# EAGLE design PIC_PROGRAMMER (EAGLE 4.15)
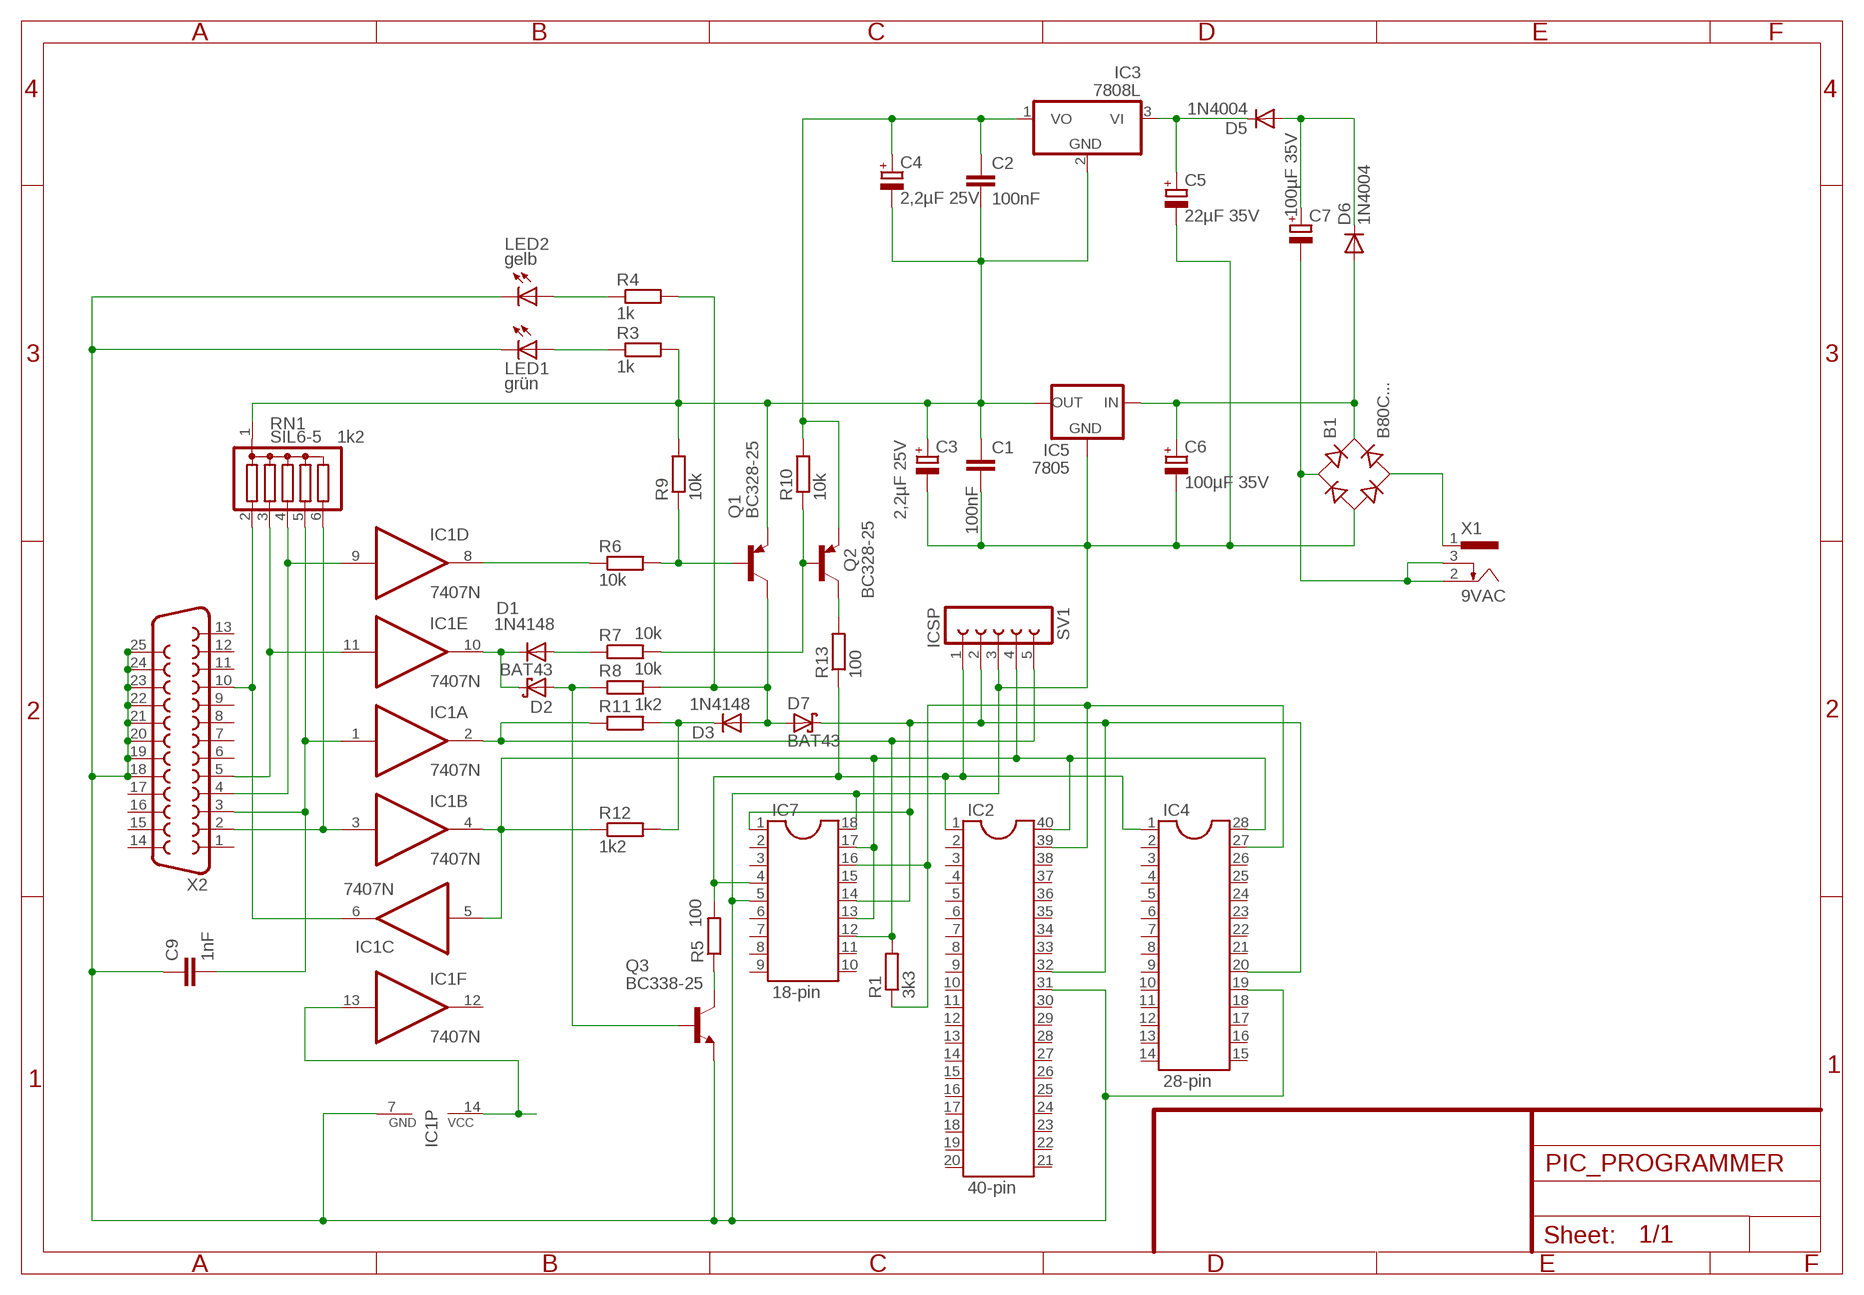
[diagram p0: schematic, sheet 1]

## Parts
B1  B80C...  RB1A  [RB1A]
C1  100nF  C-EU050-030X075  [C050-030X075]
C2  100nF  C-EU050-030X075  [C050-030X075]
C3  2,2µF 25V  CPOL-EUE2.5-5  [E2,5-5]
C4  2,2µF 25V  CPOL-EUE2.5-5  [E2,5-5]
C5  22µF 35V  CPOL-EUE5-8.5  [E5-8,5]
C6  100µF 35V  CPOL-EUE5-8.5  [E5-8,5]
C7  100µF 35V  CPOL-EUE5-8.5  [E5-8,5]
C9  1nF  C-EU050-025X075  [C050-025X075]
D1  1N4148  [DO35-10]
D2  BAT43  [DO35-10]
D3  1N4148  [DO35-10]
D5  1N4004  [DO41-10]
D6  1N4004  [DO41-10]
D7  BAT43  [DO35-10]
IC1  7407N  [DIL14]
IC2  40-pin  TEXTOOL40  [TEXTOOL40]
IC3  7808L  [TO92]
IC4  28-pin  DIL28-3  [DIL28-3]
IC5  7805  78XXS  [78XXS]
IC7  18-pin  TEXTOOL18  [TEXTOOL18]
LED1  grün  LED5MM  [LED5MM]
LED2  gelb  LED5MM  [LED5MM]
Q1  BC328-25  [TO92-EBC]
Q2  BC328-25  [TO92-EBC]
Q3  BC338-25  [TO92-EBC]
R1  3k3  R-EU_0207/10  [0207/10]
R3  1k  R-EU_0207/10  [0207/10]
R4  1k  R-EU_0207/10  [0207/10]
R5  100  R-EU_0207/10  [0207/10]
R6  10k  R-EU_0207/10  [0207/10]
R7  10k  R-EU_0207/10  [0207/10]
R8  10k  R-EU_0207/10  [0207/10]
R9  10k  R-EU_0207/10  [0207/10]
R10  10k  R-EU_0207/10  [0207/10]
R11  1k2  R-EU_0207/10  [0207/10]
R12  1k2  R-EU_0207/10  [0207/10]
R13  100  R-EU_0207/10  [0207/10]
RN1  SIL6-5 1k2  G05R  [SIL6]
SV1  ICSP  FE05-1  [FE05-1]
X1  9VAC  733989-55  [733989-5]
X2  F25H  [F25H]

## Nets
5VGESCH: D3.A D7.A Q1.C R4.2 R8.2
13V: C2.1 C4.+ IC3.1(VO) Q2.E R10.2
DATA_IN: IC1.3(B:I) RN1.6 X2.2
DATA_OUT: IC1.6(C:O) RN1.2 X2.10
GND [GND]: B1.- C1.2 C3.- C5.- C6.- C9.1 IC1.7(P:GND) IC2.31 IC4.19 IC5.GND IC7.5 IC7.18 LED1.K(C) LED2.K(C) Q3.E SV1.3 X2.18 X2.19 X2.20 X2.21 X2.22 X2.23 X2.24 X2.25
ICSP_CLK: IC1.2(A:O) IC7.12 R1.2 R11.1 SV1.5
ICSP_DATA: IC1.4(B:O) IC1.5(C:I) IC2.40 IC4.28 IC7.13 IC7.17 R12.1 SV1.4
MCLR: IC2.1 IC4.1 IC7.4 R5.2 R13.1 SV1.1
N$1: IC1.9(D:I) RN1.4 X2.4
N$2: IC1.11(E:I) RN1.3 X2.5
N$3: C9.2 IC1.1(A:I) RN1.5 X2.3
N$4: D3.C R11.2 R12.2
N$5: IC2.39 IC4.27 IC7.16 R1.1
N$6: IC1.8(D:O) R6.1
N$7: B1.+ C6.+ D6.A IC5.IN
N$8: Q2.C R13.2
N$9: B1.AC1 C7.- X1.2 X1.3
N$10: C5.+ D5.C IC3.3(VI)
N$11: C7.+ D5.A D6.C
N$12: Q3.C R5.1
N$13: B1.AC2 X1.1
N$14: D1.C D2.C IC1.10(E:O)
N$15: LED1.A R3.1
N$16: LED2.A R4.1
N$17: Q1.B R6.2 R9.1
N$18: D1.A R7.1
N$19: Q2.B R7.2 R10.1
N$21: D2.A Q3.B R8.1
VCC [GND]: C1.1 C2.2 C3.+ C4.- IC1.13(F:I) IC1.14(P:VCC) IC3.2(GND) IC5.OUT Q1.E R3.2 R9.2 RN1.1
VDD: D7.C IC2.32 IC4.20 IC7.1 IC7.14 SV1.2
Unconnected: IC1.12(F:O) IC2.2 IC2.3 IC2.4 IC2.5 IC2.6 IC2.7 IC2.8 IC2.9 IC2.10 IC2.11 IC2.12 IC2.13 IC2.14 IC2.15 IC2.16 IC2.17 IC2.18 IC2.19 IC2.20 IC2.21 IC2.22 IC2.23 IC2.24 IC2.25 IC2.26 IC2.27 IC2.28 IC2.29 IC2.30 IC2.33 IC2.34 IC2.35 IC2.36 IC2.37 IC2.38 IC4.2 IC4.3 IC4.4 IC4.5 IC4.6 IC4.7 IC4.8 IC4.9 IC4.10 IC4.11 IC4.12 IC4.13 IC4.14 IC4.15 IC4.16 IC4.17 IC4.18 IC4.21 IC4.22 IC4.23 IC4.24 IC4.25 IC4.26 IC7.2 IC7.3 IC7.6 IC7.7 IC7.8 IC7.9 IC7.10 IC7.11 IC7.15 X2.1 X2.6 X2.7 X2.8 X2.9 X2.11 X2.12 X2.13 X2.14 X2.15 X2.16 X2.17

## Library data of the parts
B1 = rectifier:RB1A: RECTIFIER 1 A
C1 C2 C9 = rcl:C-EU: CAPACITOR, European symbol
C3-C7 = rcl:CPOL-EU: POLARIZED CAPACITOR, European symbol
D1 D3 = diode:1N4148: DIODE
D2 D7 = sprut:BAT43: DIODE
D5 D6 = diode:1N4004: DIODE
IC1 = 74xx-eu:74*07: Hex BUFFER, open collector high-voltage output
IC2 = sprut:TEXTOOL40: Dual In Line
IC3 = linear:78*: Positive VOLTAGE REGULATOR
IC4 = ic-package:DIL28: Dual In Line
IC5 = v-reg:78XXS: VOLTAGE REGULATOR
IC7 = sprut:TEXTOOL18: Dual In Line
LED1 LED2 = led:LED: LED
Q1 Q2 = transistor-pnp:BC328*: PNP Transistror
Q3 = transistor-npn:BC338*: NPN Transistor
R1 R3-R13 = rcl:R-EU_: RESISTOR, European symbol
RN1 = resistor-sil:G05R: SIL RESISTOR
SV1 = con-lsta:FE05-1: FEMALE HEADER
X1 = con-conrad:733989-55: FEMALE PRINT CONNECTOR 1.1 mm, FUK HING Industries, distributor Conrad
X2 = con-subd:F25: SUB-D

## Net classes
1 GND: width 1.016 mm

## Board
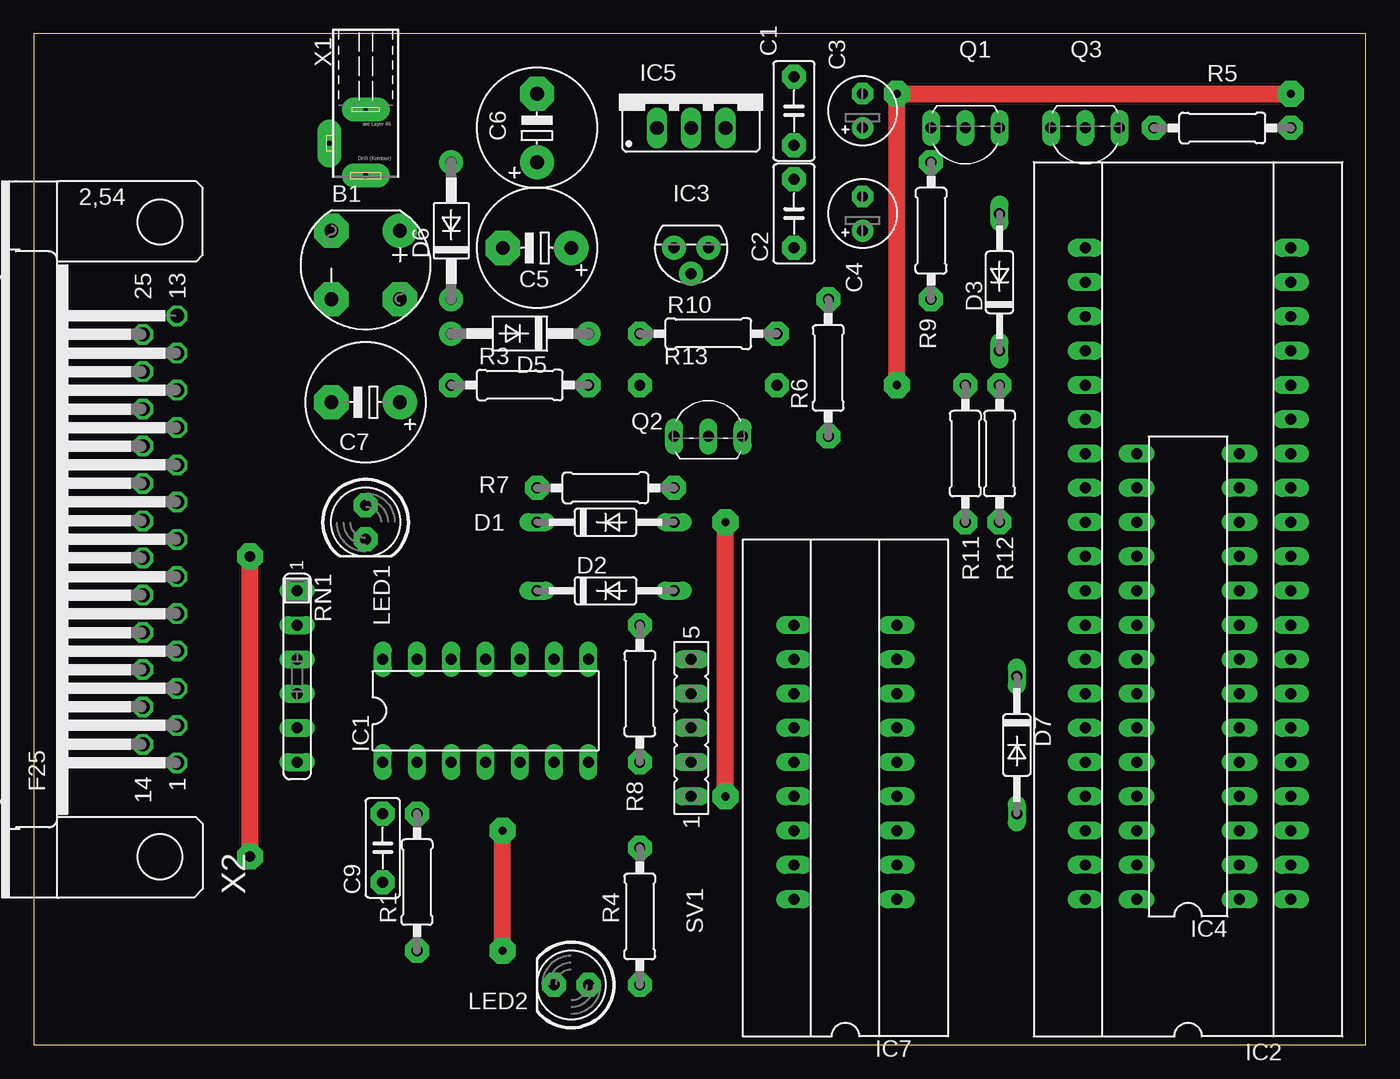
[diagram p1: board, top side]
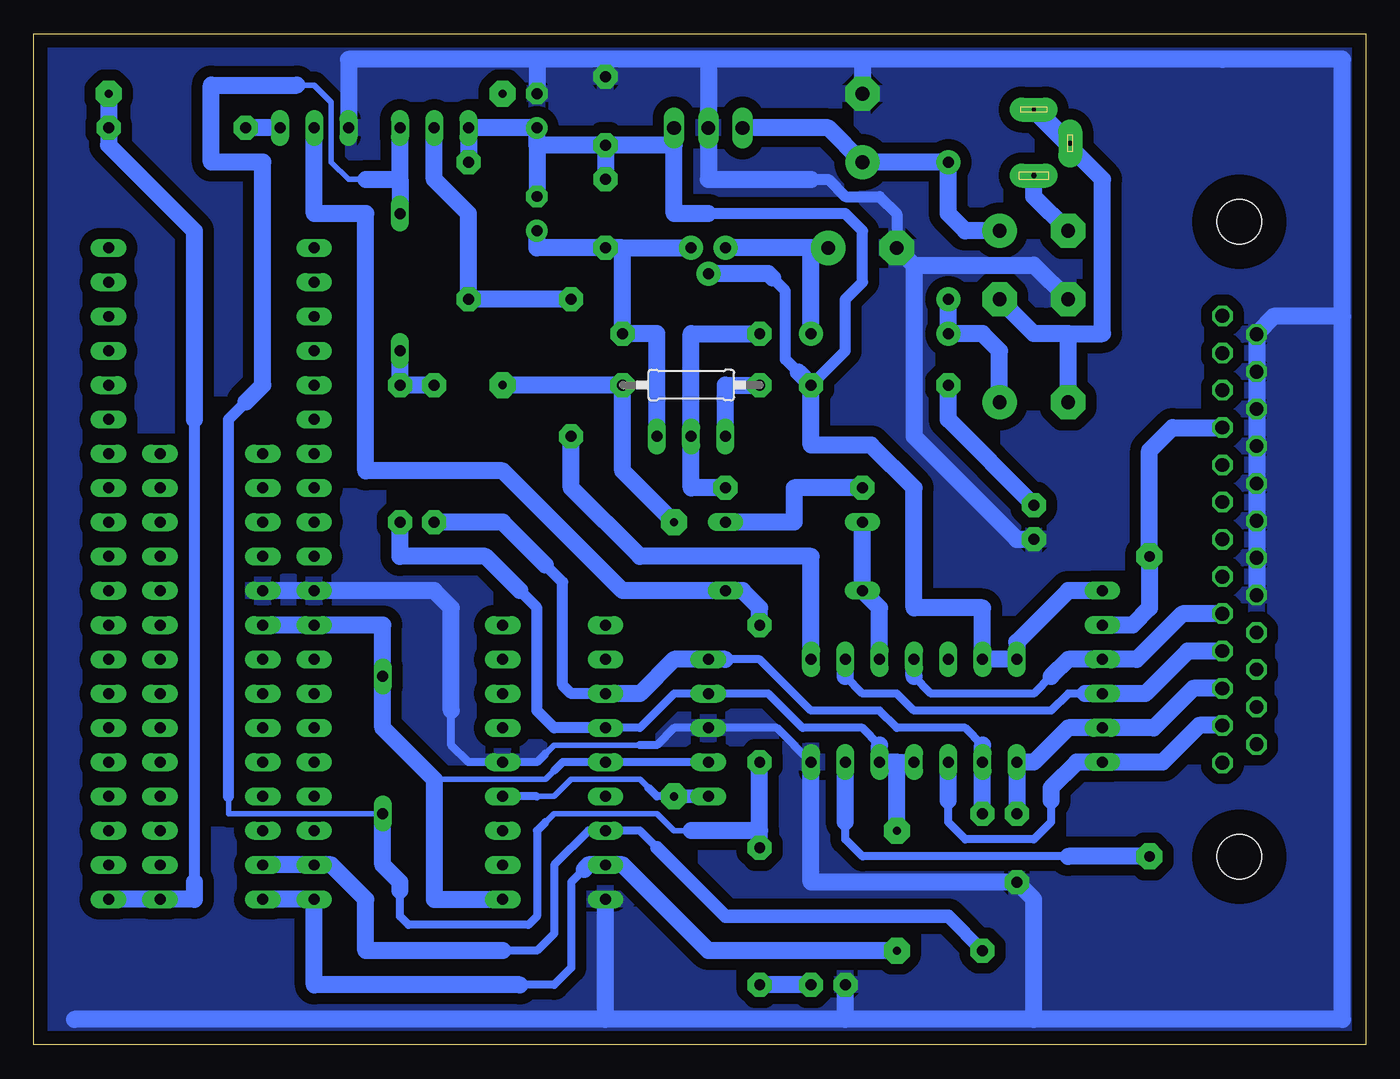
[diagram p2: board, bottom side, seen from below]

Size 98.73 x 74.92 mm. Coordinates in mm from the lower left corner, seen from the top.
Outline: 0,0 98.73,0 98.73,74.92 0,74.92 0,0
Copper layers (1*16): Top 0.035mm / dielectric 1.5mm / Bottom 0.035mm
Design rules "leiterplatte mit löchern": minimum track width 10mil, minimum drill 8mil, track to track 8mil, track to pad 8mil, pad to pad 8mil, via to via 8mil, smd to smd 8mil, copper to edge 40mil, drill to drill 8mil, minimum pad ring 10mil, minimum via ring 10mil, stop-mask expansion 4mil, vias tented up to drill 0mil, thermal gap 10mil

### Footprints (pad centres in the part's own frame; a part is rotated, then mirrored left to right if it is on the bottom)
RB1A = drill 1.016 pad 2.54 round: + -2.54,2.54 | drill 1.016 pad 2.54 octagon: - 2.54,-2.54; AC1 2.54,2.54; AC2 -2.54,-2.54
C050-030X075 = drill 0.813 pad 1.778 octagon: 1 -2.54,0; 2 2.54,0
E2,5-5 = drill 0.813 pad 1.6 round: + -1.27,0 | drill 0.813 pad 1.6 octagon: - 1.27,0
E5-8,5 = drill 1.016 pad 2.54 round: + -2.54,0 | drill 1.016 pad 2.54 octagon: - 2.54,0
C050-025X075 = drill 0.813 pad 1.778 octagon: 1 -2.54,0; 2 2.54,0
DO35-10 = drill 0.813 long: A 5.08,0; C -5.08,0
DO41-10 = drill 0.813 pad 1.778 round: A 5.08,0; C -5.08,0
DIL14 = drill 0.813 long: 1 -7.62,-3.81; 2 -5.08,-3.81; 3 -2.54,-3.81; 4 0,-3.81; 5 2.54,-3.81; 6 5.08,-3.81; 7 7.62,-3.81; 8 7.62,3.81; 9 5.08,3.81; 10 2.54,3.81; 11 0,3.81; 12 -2.54,3.81; 13 -5.08,3.81; 14 -7.62,3.81
TEXTOOL40 = drill 0.813 long: 1 -24.13,-7.62; 2 -21.59,-7.62; 3 -19.05,-7.62; 4 -16.51,-7.62; 5 -13.97,-7.62; 6 -11.43,-7.62; 7 -8.89,-7.62; 8 -6.35,-7.62; 9 -3.81,-7.62; 10 -1.27,-7.62; 11 1.27,-7.62; 12 3.81,-7.62; 13 6.35,-7.62; 14 8.89,-7.62; 15 11.43,-7.62; 16 13.97,-7.62; 17 16.51,-7.62; 18 19.05,-7.62; 19 21.59,-7.62; 20 24.13,-7.62; 21 24.13,7.62; 22 21.59,7.62; 23 19.05,7.62; 24 16.51,7.62; 25 13.97,7.62; 26 11.43,7.62; 27 8.89,7.62; 28 6.35,7.62; 29 3.81,7.62; 30 1.27,7.62; 31 -1.27,7.62; 32 -3.81,7.62; 33 -6.35,7.62; 34 -8.89,7.62; 35 -11.43,7.62; 36 -13.97,7.62; 37 -16.51,7.62; 38 -19.05,7.62; 39 -21.59,7.62; 40 -24.13,7.62
TO92 = drill 0.813 pad 1.778 round: 1 -1.27,0; 2 0,1.905; 3 1.27,0
DIL28-3 = drill 0.813 long: 1 -16.51,-3.81; 2 -13.97,-3.81; 3 -11.43,-3.81; 4 -8.89,-3.81; 5 -6.35,-3.81; 6 -3.81,-3.81; 7 -1.27,-3.81; 8 1.27,-3.81; 9 3.81,-3.81; 10 6.35,-3.81; 11 8.89,-3.81; 12 11.43,-3.81; 13 13.97,-3.81; 14 16.51,-3.81; 15 16.51,3.81; 16 13.97,3.81; 17 11.43,3.81; 18 8.89,3.81; 19 6.35,3.81; 20 3.81,3.81; 21 1.27,3.81; 22 -1.27,3.81; 23 -3.81,3.81; 24 -6.35,3.81; 25 -8.89,3.81; 26 -11.43,3.81; 27 -13.97,3.81; 28 -16.51,3.81
78XXS = drill 1.016 long: GND 0,-2.54; IN -2.54,-2.54; OUT 2.54,-2.54
TEXTOOL18 = drill 0.813 long: 1 -10.16,-3.81; 2 -7.62,-3.81; 3 -5.08,-3.81; 4 -2.54,-3.81; 5 0,-3.81; 6 2.54,-3.81; 7 5.08,-3.81; 8 7.62,-3.81; 9 10.16,-3.81; 10 10.16,3.81; 11 7.62,3.81; 12 5.08,3.81; 13 2.54,3.81; 14 0,3.81; 15 -2.54,3.81; 16 -5.08,3.81; 17 -7.62,3.81; 18 -10.16,3.81
LED5MM = drill 0.813 pad 1.778 octagon: A -1.27,0; K 1.27,0
TO92-EBC = drill 0.813 long: B 0,-1.27; C -2.54,-1.27; E 2.54,-1.27
0207/10 = drill 0.813 pad 1.778 octagon: 1 -5.08,0; 2 5.08,0
SIL6 = drill 0.813 long: 1 -6.35,0; 2 -3.81,0; 3 -1.27,0; 4 1.27,0; 5 3.81,0; 6 6.35,0
FE05-1 = drill 0.813 long: 1 -5.08,0; 2 -2.54,0; 3 0,0; 4 2.54,0; 5 5.08,0
733989-5 = drill 0.4 pad 1.778 long: 1 0,5.82; 3 2.7,3.42 | drill 0.3 pad 1.778 long: 2 0,0.92
F25H = drill 1.016 octagon: 1 -16.561,-1.27; 2 -13.792,-1.27; 3 -11.049,-1.27; 4 -8.28,-1.27; 5 -5.512,-1.27; 6 -2.769,-1.27; 7 0,-1.27; 8 2.769,-1.27; 9 5.512,-1.27; 10 8.28,-1.27; 11 11.049,-1.27; 12 13.792,-1.27; 13 16.561,-1.27; 14 -15.189,1.27; 15 -12.421,1.27; 16 -9.652,1.27; 17 -6.909,1.27; 18 -4.14,1.27; 19 -1.372,1.27; 20 1.372,1.27; 21 4.14,1.27; 22 6.909,1.27; 23 9.652,1.27; 24 12.421,1.27; 25 15.189,1.27 | hole 3.302: -23.52,0; 23.52,0

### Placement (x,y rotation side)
B1  24.6,57.78 270 top
C1  56.35,69.21 90 top
C2  56.35,61.59 90 top
C3  61.43,69.21 90 top
C4  61.43,61.59 90 top
C5  37.3,59.05 180 top
C6  37.3,67.94 90 top
C7  24.6,47.62 180 top
C9  25.87,14.6 90 top
D1  42.38,38.73 0 top
D2  42.38,33.65 0 top
D3  71.59,56.51 90 top
D5  36.03,52.7 180 top
D6  30.95,60.32 90 top
D7  72.86,22.22 270 top
IC1  33.49,24.76 0 top
IC2  85.56,34.92 90 top
IC3  48.73,59.05 180 top
IC4  85.56,27.3 90 top
IC5  48.73,70.48 0 top
IC7  60.16,20.95 90 top
LED1  24.6,38.73 270 top
LED2  39.84,4.44 180 top
Q1  69.05,66.67 180 top
Q2  50,46.35 0 top
Q3  77.94,66.67 180 top
R1  28.41,12.06 90 top
R3  36.03,48.89 0 top
R4  44.92,9.52 90 top
R5  88.1,67.94 0 top
R6  58.89,50.16 90 top
R7  42.38,41.27 0 top
R8  44.92,26.03 270 top
R9  66.51,60.32 90 top
R10  50,52.7 0 top
R11  69.05,43.81 90 top
R12  71.59,43.81 90 top
R13  50,48.89 0 bottom
RN1  19.52,27.3 270 top
SV1  48.73,23.49 90 top
X1  24.6,70.23 180 top
X2  9.36,37.46 90 top

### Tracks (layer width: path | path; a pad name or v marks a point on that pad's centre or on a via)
5VGESCH
  Bottom 0.406: D7.A 84.29,17.14 84.29,18.41 | 74.13,64.13 75.4,64.13 76.67,65.4 76.67,69.84 77.94,71.12 79.21,71.12 | 50,15.87 51.27,15.87 52.54,17.14 60.16,17.14 60.8,16.5
  Bottom 0.61: 71.59,11.43 71.59,9.52 70.95,8.88 62.07,8.88 61.43,9.52 61.43,15.87 60.8,16.5
  Bottom 0.813: 83.02,47.62 84.29,46.35 84.29,18.41
  Bottom 1.27: R4.2 44.92,15.87 | 44.92,15.87 R8.2 | D7.A 72.86,13.33 71.59,12.06 71.59,11.43 | 71.59,64.13 Q1.C | 71.59,64.13 D3.A | 74.13,64.13 71.59,64.13 | 79.21,71.12 85.56,71.12 85.56,65.4 81.75,65.4 81.75,48.89 83.02,47.62 | 44.92,15.87 50,15.87
13V
  Bottom 1.27: 55.08,59.05 IC3.1 | 55.08,59.05 C2.1 61.43,59.05 C4.+ | 55.08,59.05 R10.2 52.54,52.7 Q2.E
DATA_IN
  Bottom 0.61: 30.95,18.09 30.95,16.5 29.68,15.23 24.6,15.23 23.33,16.5 23.33,18.09
  Bottom 1.27: 30.95,18.09 IC1.3 | 23.33,18.09 23.33,19.04 21.43,20.95 RN1.6 15.07,20.95 12.35,23.68 10.66,23.68 X2.2
DATA_OUT  (via drill 0.8 pad 1.93)
  Top 1.27: v16.03,13.96 v16.03,36.19
  Bottom 0.61: 22.06,13.96 37.3,13.96 38.57,15.23 38.57,16.5
  Bottom 1.27: 38.57,16.5 IC1.6 | X2.10 14.33,45.74 16.03,44.03 v16.03,36.19 16.03,32.38 17.3,31.11 RN1.2 | v16.03,13.96 22.06,13.96
GND
  Bottom 0.406: 60.8,21.59 60.16,22.22 53.81,22.22
  Bottom 0.61: IC1.7 43.65,23.49 SV1.3 51.27,23.49 52.54,22.22 53.81,22.22 | 1.74,73.02 1.76,73.05 | 60.8,21.59 61.43,20.95 IC7.5 66.51,20.95 67.78,22.22 67.78,24.76
  Bottom 0.813: 41.11,64.13 39.84,64.13 38.57,62.86 36.03,62.86 34.76,61.59 C5.-
  Bottom 1.27: 24.6,1.9 1.74,1.9 1.74,53.97 | 24.6,1.9 38.57,1.9 | 38.57,1.9 56.35,1.9 | 56.35,1.9 95.72,1.9 | 1.74,53.97 1.74,73.02 | IC4.19 IC2.31 69.05,33.65 67.78,32.38 67.78,24.76 | 56.35,1.9 IC7.18 | IC1.7 41.11,12.06 C9.1 24.6,10.79 24.6,1.9 | 38.57,1.9 LED2.K | 37.3,73.02 C6.- | 37.3,73.02 48.73,73.02 | 48.73,73.02 IC5.GND 48.73,64.13 41.11,64.13 | B1.- 24.6,57.78 33.49,57.78 | C5.- 33.49,57.78 | 1.76,73.05 10.63,73.02 37.3,73.02 | 56.35,73.02 C1.2 | 61.43,73.02 C3.- | 56.35,73.02 61.43,73.02 | 48.73,73.02 56.35,73.02 | Q3.E 75.4,73.02 61.43,73.02 | LED1.K 25.87,37.46 33.49,45.08 33.49,57.78 | 1.74,53.97 6.82,53.97 8.09,52.7 X2.25 X2.24 8.09,47.62 | 8.09,47.62 X2.23 | 8.09,47.62 X2.22 X2.21 | X2.21 8.09,41.59 | X2.20 8.09,38.73 | X2.21 X2.20 | X2.20 X2.19 X2.18
  pour Bottom (isolate 0.813): -2.07,-0.64 99.53,-0.64 99.53,75.56 -2.07,75.56
ICSP_CLK
  Bottom 0.61: 28.41,22.22 29.68,23.49 34.76,23.49 36.03,24.76 41.11,24.76 44.92,28.57 47.46,28.57
  Bottom 0.813: 60.8,35.56 59.53,34.29 59.53,26.66 58.89,26.03 IC7.12
  Bottom 1.27: 28.41,22.22 IC1.2 R1.2 | IC7.12 53.81,26.03 51.27,28.57 SV1.5 47.46,28.57 | R11.1 63.97,38.73 60.8,35.56
ICSP_DATA  (via drill 0.61 pad 1.93)
  Top 1.27: v34.76,6.98 v34.76,15.87
  Bottom 0.61: 36.03,22.22 37.3,23.49 41.75,23.49 44.29,26.03 SV1.4 51.27,26.03 53.81,23.49 IC7.13 | 62.7,4.44 60.16,4.44 58.89,5.71 58.89,12.06 57.94,13.01
  Bottom 0.813: 62.7,33.65 61.43,32.38 61.43,24.76 60.16,23.49 IC7.13
  Bottom 1.27: 34.76,20.95 IC1.4 | 34.76,20.95 IC1.5 36.03,22.22 | IC4.28 IC2.40 77.94,4.44 62.7,4.44 | v34.76,6.98 48.73,6.98 55.08,13.33 IC7.17 57.62,13.33 57.94,13.01 | v34.76,15.87 34.76,20.95 | R12.1 71.59,36.19 65.24,36.19 62.7,33.65
MCLR  (via drill 0.61 pad 1.93)
  Top 1.27: v51.27,18.41 v51.27,38.73 | v63.97,48.89 v63.97,70.48 v93.18,70.48
  Bottom 0.406: 61.43,18.41 60.16,18.41 58.89,19.68 53.81,19.68 53.18,19.04
  Bottom 0.61: 61.43,18.41 IC7.4 | 53.18,19.04 52.54,18.41 v51.27,18.41
  Bottom 0.813: 86.83,46.35 86.83,12.06
  Bottom 1.016: SV1.1 v51.27,18.41
  Bottom 1.27: IC2.1 IC4.1 86.83,10.79 86.83,12.06 | 86.83,46.35 86.83,60.32 93.18,66.67 R5.2 v93.18,70.48 | R13.1 55.08,42.54 v51.27,38.73 | R13.1 v63.97,48.89 R13.1
N$1
  Bottom 0.61: 38.57,27.3 37.3,26.03 34.76,26.03 33.49,24.76 23.33,24.76 22.06,26.03 20.79,26.03
  Bottom 1.27: 38.57,27.3 IC1.9 | 20.79,26.03 RN1.4 16.34,26.03 13.19,29.18 10.68,29.18 X2.4
N$2
  Bottom 0.61: 33.49,27.3 32.22,26.03 24.6,26.03 23.33,27.3
  Bottom 1.27: 33.49,27.3 IC1.11 | 23.33,27.3 22.06,28.57 RN1.3 16.98,28.57 13.59,31.94 10.74,31.94 X2.5
N$3
  Bottom 1.27: C9.2 IC1.1 24.6,20.95 22.06,23.49 RN1.5 15.71,23.49 12.79,26.41 10.71,26.41 X2.3
N$4
  Bottom 1.27: R11.2 R12.2 D3.C
N$5
  Bottom 0.61: 63.97,6.98 61.43,6.98 60.16,8.25 60.16,13.33 57.62,15.87 IC7.16 53.81,15.87 52.54,14.6
  Bottom 1.016: R1.1 30.95,9.52 47.46,9.52 52.54,14.6
  Bottom 1.27: IC4.27 IC2.39 76.67,13.33 74.13,10.79 74.13,6.98 63.97,6.98
N$6
  Bottom 1.27: R6.1 58.89,41.27 53.81,36.19 41.11,36.19 IC1.8
N$7
  Bottom 1.27: IC5.IN 39.84,67.94 C6.+ D6.A 30.95,61.59 29.68,60.32 B1.+
N$8
  Bottom 1.27: Q2.C 47.46,48.89 R13.2
N$9
  Bottom 0.61: X1.2 24.7,69.31 24.6,69.21 | 24.46,69.35 22.06,66.67 | 21.9,66.51 X1.3
  Bottom 1.27: 22.06,52.7 24.6,52.7 B1.AC1 | C7.- 22.06,52.7 | X1.3 24.46,69.35 | 22.06,66.67 24.6,69.21 | 21.9,66.51 19.52,64.13 19.52,52.7 22.06,52.7
N$10
  Bottom 1.27: D5.C 41.11,59.05 C5.+ IC3.3
N$11
  Bottom 1.27: D6.C D5.A 28.41,52.7 27.14,51.43 C7.+
N$12
  Bottom 1.27: Q3.C R5.1
N$13
  Bottom 1.27: B1.AC2 24.6,62.86 X1.1
N$14
  Bottom 1.27: IC1.10 36.03,32.38 D2.C D1.C
N$15
  Bottom 1.27: LED1.A 30.95,46.35 R3.1
N$16
  Bottom 1.27: LED2.A R4.1
N$17
  Bottom 1.27: Q1.B 69.05,64.13 66.51,61.59 R9.1 R6.2
N$18
  Bottom 1.27: R7.1 42.38,41.27 42.38,38.73 D1.A
N$19
  Bottom 1.27: R10.1 50,52.7 Q2.B 50,41.27 R7.2
N$21
  Bottom 1.27: Q3.B 77.94,61.59 74.13,61.59 74.13,42.54 63.97,42.54 55.08,33.65 D2.A 46.19,33.65 44.92,32.38 R8.1
VCC
  Bottom 0.813: 48.73,61.59 38.57,61.59 37.3,60.32 37.3,56.51 38.57,55.24 38.57,51.43 R3.2 | 43.97,56.83 43.02,55.88 43.02,50.8 42.06,49.84
  Bottom 1.27: IC1.14 IC1.13 | IC1.14 25.87,29.84 22.06,33.65 RN1.1 | IC1.14 IC1.13 | IC1.13 28.41,32.38 33.49,32.38 33.49,41.27 36.67,44.45 41.11,44.45 R3.2 42.06,49.84 | 48.73,61.59 51.27,61.59 51.27,66.67 | 51.27,66.67 IC5.OUT | C1.1 C2.2 | 51.27,66.67 C1.1 | C1.1 61.43,66.67 | 61.43,66.67 C3.+ Q1.E R9.2 | 61.43,66.67 C4.- | IC3.2 44.29,57.15 43.97,56.83
VDD
  Bottom 0.406: 60.16,20.32 60.8,19.68 69.05,19.68
  Bottom 0.61: SV1.2 IC7.14 59.53,20.95 60.16,20.32
  Bottom 1.27: IC4.20 IC2.32 72.86,31.11 D7.C 72.86,23.49 69.05,19.68 69.05,10.79 IC7.1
